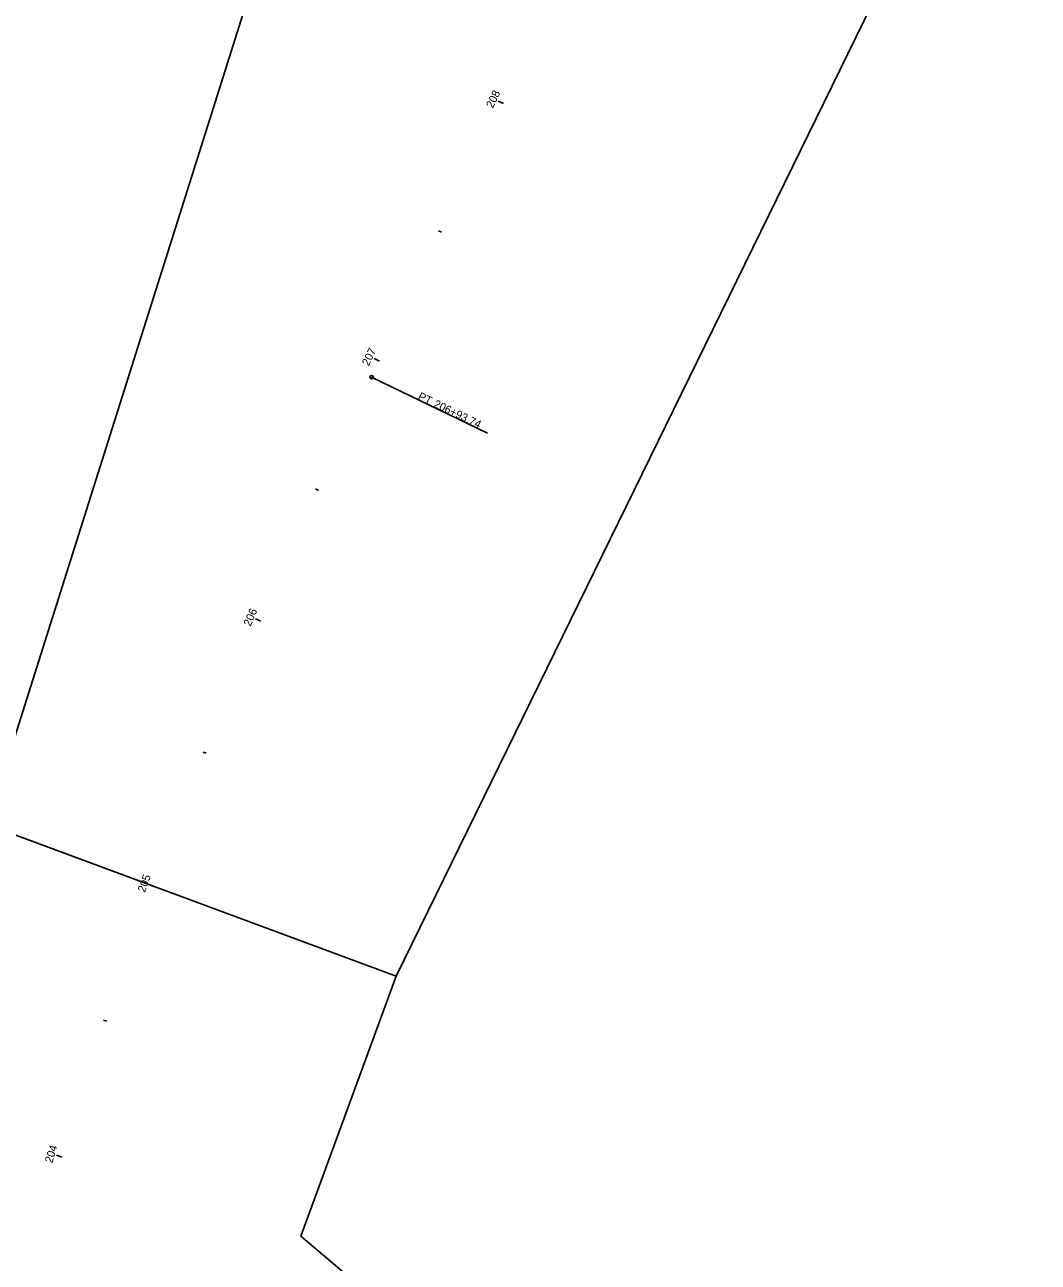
# Model space of a CAD drawing. Extents: x 1564517 to 1565226, y 635740 to 637455.
# Drawn here: x 1564871.5 to 1565225.9, y 636589.4 to 637022.2 of the extents above; entities that cross this region are included whole.
import ezdxf

# ---------------------------------------------------------------- set-up
doc = ezdxf.new("R2010")
doc.units = 0
for name, color, linetype in [('GE_P_Alignment_1000_Cardinal_Points', 7, 'Continuous'), ('GE_P_Alignment_1000_Stations', 7, 'Continuous'), ('GE_P_Alignment_100_Cardinal_Points', 7, 'Continuous'), ('GE_P_Alignment_100_Stations', 7, 'Continuous'), ('GE_P_Alignment_500_Cardinal_Points', 7, 'Continuous'), ('GE_P_Alignment_500_Stations', 7, 'Continuous'), ('SH_Named_Boundary', 7, 'Continuous')]:
    doc.layers.add(name, color=color, linetype=linetype)

msp = doc.modelspace()

# ---------------------------------------------------------------- linework, layer by layer
at = {"layer": 'GE_P_Alignment_1000_Cardinal_Points'}
msp.add_line((1564992.79, 636898.95), (1565033.33, 636879.42), dxfattribs=at)
msp.add_circle((1564992.79, 636898.95), 0.6, dxfattribs=at)
at = {"layer": 'GE_P_Alignment_1000_Stations'}
msp.add_line((1564916.98, 636720.72), (1564915.86, 636721.14), dxfattribs=at)
at = {"layer": 'GE_P_Alignment_100_Cardinal_Points'}
msp.add_line((1564992.79, 636898.95), (1565033.33, 636879.42), dxfattribs=at)
msp.add_circle((1564992.79, 636898.95), 0.6, dxfattribs=at)
at = {"layer": 'GE_P_Alignment_100_Stations'}
for p, q in [((1565038.89, 636994.68), (1565037.09, 636995.55)), ((1565017.2, 636949.63), (1565016.12, 636950.15)), ((1564995.5, 636904.58), (1564993.7, 636905.45)), ((1564974.22, 636859.34), (1564973.13, 636859.84)), ((1564954.03, 636813.6), (1564952.19, 636814.38)), ((1564934.95, 636767.38), (1564933.83, 636767.83)), ((1564916.98, 636720.72), (1564915.11, 636721.42)), ((1564900.15, 636673.64), (1564899.01, 636674.04)), ((1564884.45, 636626.17), (1564882.55, 636626.78))]:
    msp.add_line(p, q, dxfattribs=at)
at = {"layer": 'GE_P_Alignment_500_Cardinal_Points'}
msp.add_line((1564992.79, 636898.95), (1565033.33, 636879.42), dxfattribs=at)
msp.add_circle((1564992.79, 636898.95), 0.6, dxfattribs=at)
at = {"layer": 'GE_P_Alignment_500_Stations'}
for p, q in [((1565038.89, 636994.68), (1565037.81, 636995.2)), ((1564995.5, 636904.58), (1564994.42, 636905.1)), ((1564954.03, 636813.6), (1564952.93, 636814.07)), ((1564916.98, 636720.72), (1564915.11, 636721.42)), ((1564884.45, 636626.17), (1564883.31, 636626.54))]:
    msp.add_line(p, q, dxfattribs=at)
at = {"layer": 'SH_Named_Boundary'}
for points in [[(1564858.24, 636742.53), (1565001.39, 636689.39), (1565225.94, 637148.15), (1565017.94, 637248.32)], [(1564617.12, 636229.41), (1564988.09, 636191.25), (1564943.69, 636230.5), (1564972.57, 636431.98), (1565013.42, 636482), (1565021.18, 636553.46), (1564968.04, 636598.47), (1565001.39, 636689.39), (1564864.83, 636740.08), (1564842.01, 636748.56), (1564682.06, 636752.05), (1564640.72, 636336.77)]]:
    msp.add_lwpolyline(points, close=True, dxfattribs=at)

# ---------------------------------------------------------------- texts
at = {"layer": 'GE_P_Alignment_1000_Cardinal_Points'}
for s, p in [('PT', (1565008.74, 636891.31)), ('206+93.74', (1565014.22, 636888.67))]:
    msp.add_text(s, height=2.8, rotation=334.2844, dxfattribs=at).set_placement(p)
at = {"layer": 'GE_P_Alignment_100_Cardinal_Points'}
for s, p in [('PT', (1565008.74, 636891.31)), ('206+93.74', (1565014.22, 636888.67))]:
    msp.add_text(s, height=2.8, rotation=334.2844, dxfattribs=at).set_placement(p)
at = {"layer": 'GE_P_Alignment_100_Stations'}
for s, rotation, p in [('208', 64.2844, (1565035.17, 636992.83)), ('207', 64.2844, (1564991.76, 636902.68)), ('206', 66.8724, (1564950.4, 636811.58)), ('205', 69.633, (1564913.45, 636718.52)), ('204', 72.3937, (1564881.05, 636623.86))]:
    msp.add_text(s, height=2.8, rotation=rotation, dxfattribs=at).set_placement(p)
at = {"layer": 'GE_P_Alignment_500_Cardinal_Points'}
for s, p in [('PT', (1565008.74, 636891.31)), ('206+93.74', (1565014.22, 636888.67))]:
    msp.add_text(s, height=2.8, rotation=334.2844, dxfattribs=at).set_placement(p)
at = {"layer": 'GE_P_Alignment_500_Stations'}
msp.add_text('205', height=2.8, rotation=69.633, dxfattribs=at).set_placement((1564913.45, 636718.52))

doc.saveas('drawing.dxf')
